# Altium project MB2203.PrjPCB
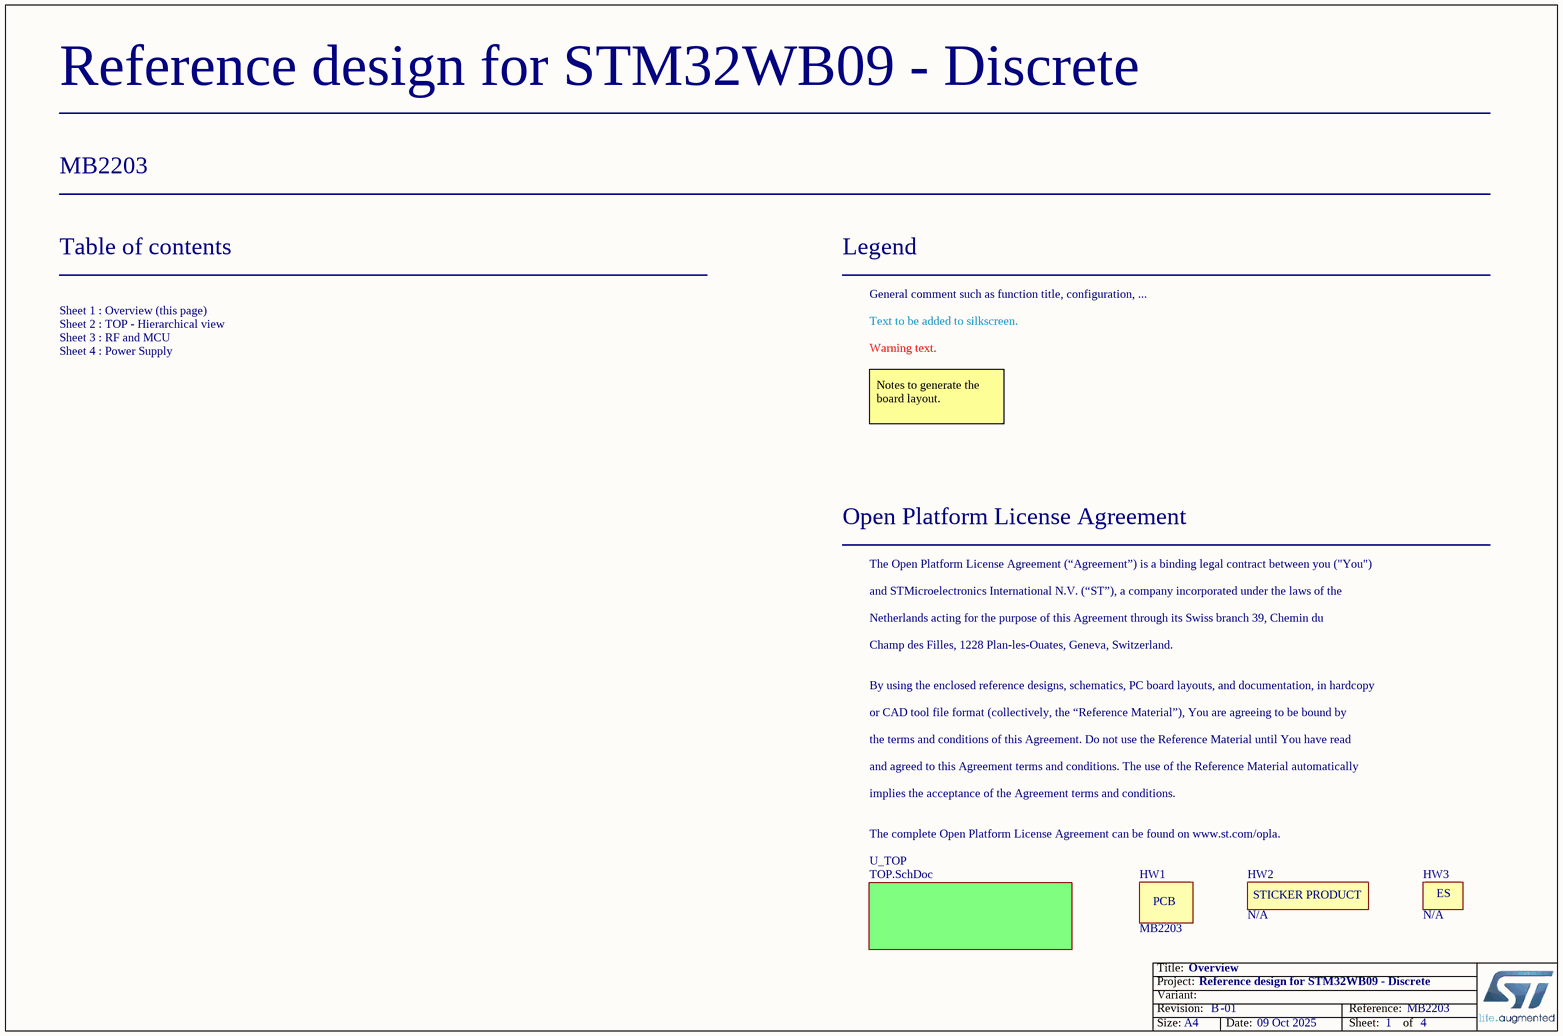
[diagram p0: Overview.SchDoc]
Board_Assembly_Revision: 01; Board_Document_Date: 09 Oct 2025; Board_Name: Reference design for STM32WB09 - Discrete; Board_PCB_Revision: B; Board_Reference: MB2203
4 sheets, 43 parts. Net scope: global (net labels, ports and power ports of the same name join across sheets).
Board file: MB2203.PcbDoc
Sheets:
  Overview.SchDoc
    U_TOP = TOP.SchDoc
      U_RF_MCU = RF_MCU.SchDoc
      U_Power_Supply = Power_Supply.SchDoc

## Sheet Overview.SchDoc: Overview
size A4; Date: Not used; ApprovedBy: Not used; CheckedBy: Not used; Author: Not used; CompanyName: STMicroelectronics; DrawnBy: Not used; Engineer: Not used; Organization: Not used; Address1: Not used; Address2: Not used; Address3: Not used; Address4: Not used; DocumentNumber: 1; Revision: Not used; SheetNumber: 1; SheetTotal: 4

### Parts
HW1  value MB2203  (hidden comment: PCB)
HW2  STICKER_PRODUCT  [STICKER_PRODUCT_25X9]  (value not drawn)  (no BOM)
HW3  STICKER_ES  [STICKER_ES_6X6]  (value not drawn)  (no BOM)

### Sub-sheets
U_TOP = TOP.SchDoc: no entries

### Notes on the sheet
- Table of contents
- Legend
- General comment such as function title, configuration, ...
- Text to be added to silkscreen.
- Warning text.
- Notes to generate the board layout.
- Open Platform License Agreement
- The Open Platform License Agreement (“Agreement”) is a binding legal contract between you ("You")
- and STMicroelectronics International N.V. (“ST”), a company incorporated under the laws of the
- Netherlands acting for the purpose of this Agreement through its Swiss branch 39, Chemin du
- Champ des Filles, 1228 Plan-les-Ouates, Geneva, Switzerland.
- Sheet 1 : Overview (this page)
  Sheet 2 : TOP - Hierarchical view
  Sheet 3 : RF and MCU
  Sheet 4 : Power Supply
- By using the enclosed reference designs, schematics, PC board layouts, and documentation, in hardcopy
- or CAD tool file format (collectively, the “Reference Material”), You are agreeing to be bound by
- the terms and conditions of this Agreement. Do not use the Reference Material until You have read
- and agreed to this Agreement terms and conditions. The use of the Reference Material automatically
- implies the acceptance of the Agreement terms and conditions.
- The complete Open Platform License Agreement can be found on www.st.com/opla.

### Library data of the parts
HW1 = MCD-04954: PCB, MB2203, 41x31mm, 4L1S, 0.638mm, TG150, VT-47; Part_Preference: Recommended; Manufacturer: SYNERGIE CAD; ShowFields: YES; ID: 7070
HW2 = MCD-00547: Sticker product, 25x9mm; Part_Type: Misc; Part_Preference: Recommended; Component_Country_Of_Origin: Unknown; ShowFields: YES; ID: 3197
HW3 = MCD-00234: Sticker ES, 6x6mm; Part_Type: Misc; Part_Preference: Recommended; Component_Country_Of_Origin: Unknown; ShowFields: YES; ID: 2634

## Sheet TOP.SchDoc: TOP - Hierarchical view
size A4; Date: Not used; ApprovedBy: Not used; CheckedBy: Not used; Author: Not used; CompanyName: STMicroelectronics; DrawnBy: Not used; Engineer: Not used; Organization: Not used; Address1: Not used; Address2: Not used; Address3: Not used; Address4: Not used; DocumentNumber: Not used; Revision: Not used; SheetNumber: 2; SheetTotal: 4
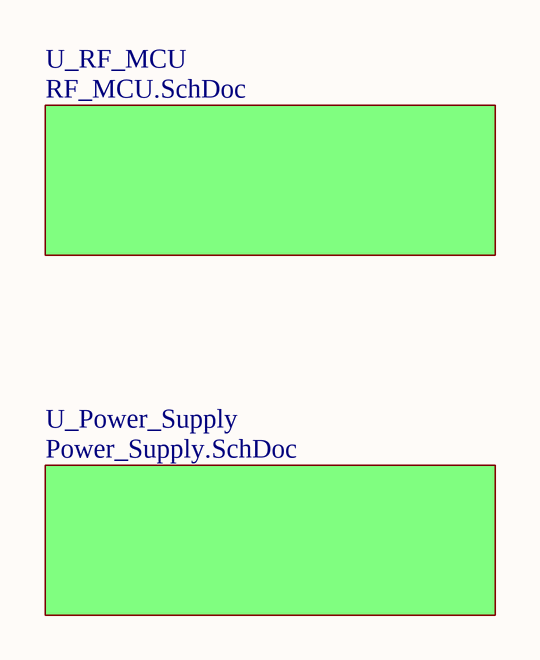
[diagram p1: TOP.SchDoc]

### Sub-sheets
U_Power_Supply = Power_Supply.SchDoc: no entries
U_RF_MCU = RF_MCU.SchDoc: no entries

## Sheet RF_MCU.SchDoc: RF and MCU
size A4; Date: Not used; ApprovedBy: Not used; CheckedBy: Not used; Author: Not used; CompanyName: STMicroelectronics; DrawnBy: Not used; Engineer: Not used; Organization: Not used; Address1: Not used; Address2: Not used; Address3: Not used; Address4: Not used; DocumentNumber: Not used; Revision: Not used; SheetNumber: 3; SheetTotal: 4
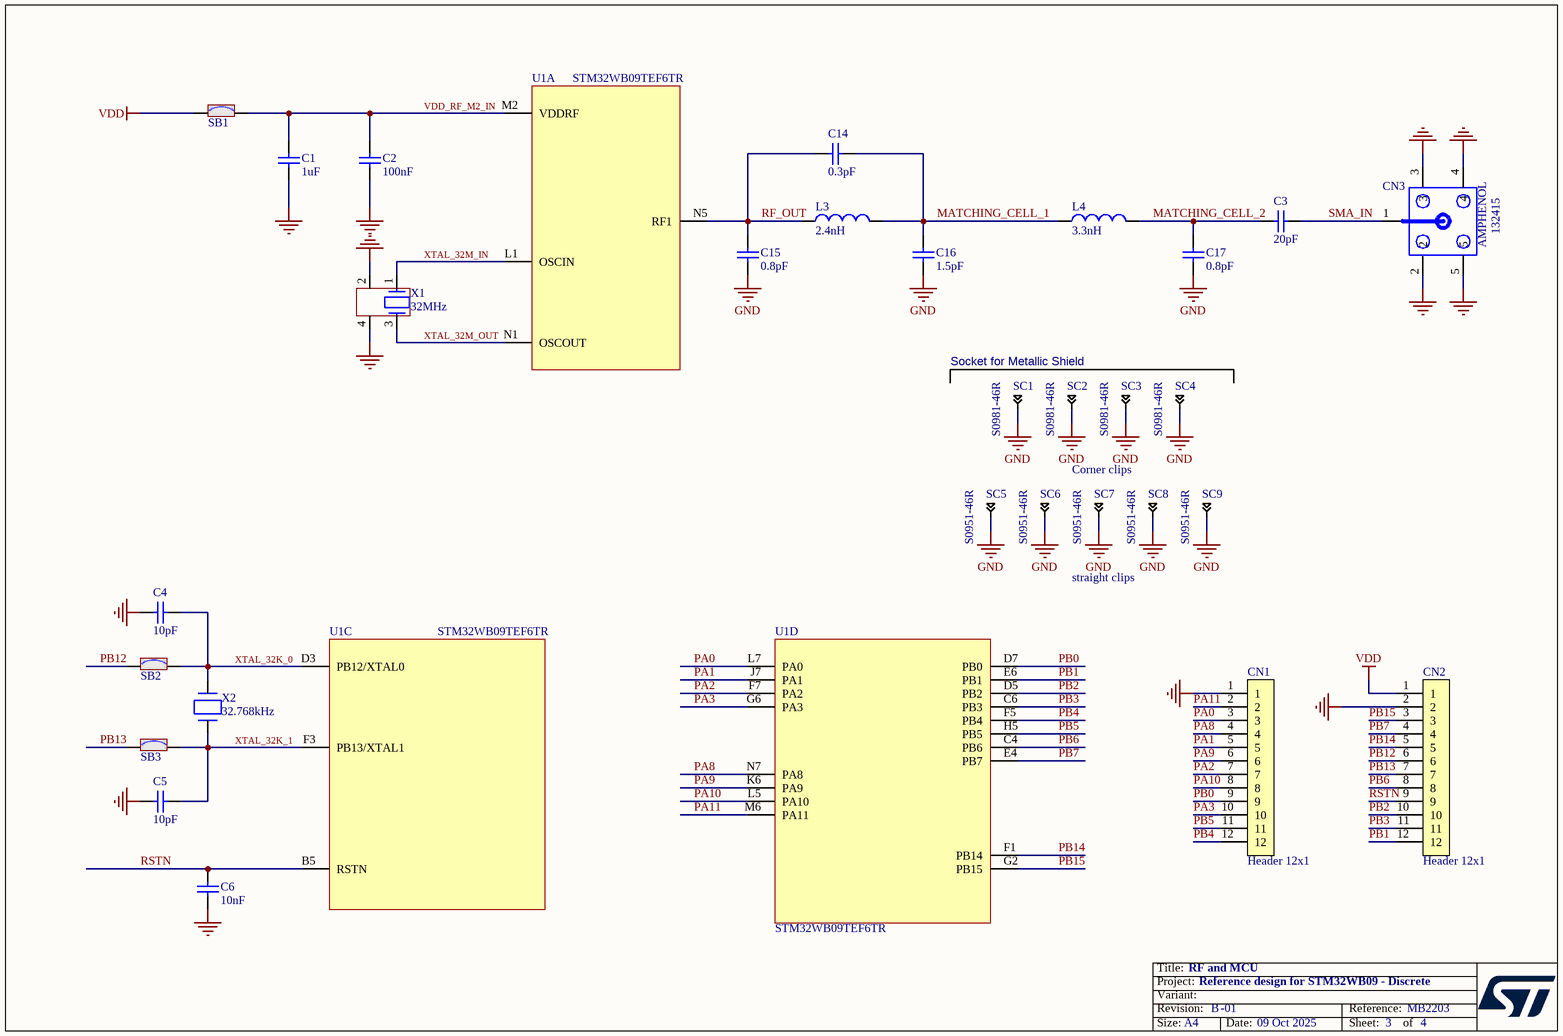
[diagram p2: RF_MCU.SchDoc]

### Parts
C1  value 1uF  [C0402]  (hidden comment: Capacitor)
C2  value 100nF  [C0201_H0P3]  (hidden comment: Capacitor)
C3  value 20pF  [C0201_H0P3]  (hidden comment: Capacitor)
C4  value 10pF  [C0402]  (hidden comment: Capacitor)
C5  value 10pF  [C0402]  (hidden comment: Capacitor)
C6  value 10nF  [C0402]  (hidden comment: Capacitor)
C14  value 0.3pF  [C0201_H0P3]  (hidden comment: Capacitor)
C15  value 0.8pF  [C0201_H0P3]  (hidden comment: Capacitor)
C16  value 1.5pF  [C0201_H0P3]  (hidden comment: Capacitor)
C17  value 0.8pF  [C0201_H0P3]  (hidden comment: Capacitor)
CN1  Header 12x1  [CON_SAMTEC_TSW-112-07-X-S]
CN2  Header 12x1  [CON_SAMTEC_TSW-112-07-X-S]
CN3  value 132415  Manufacturer: AMPHENOL  [CON_SMA_AMPHENOL_132415]  (hidden comment: SMA-J-P-H-ST-EM1)
L3  value 2.4nH  [IND_0201_MURATA_LQP03TN_H0P3]  (hidden comment: Inductor)
L4  value 3.3nH  [IND_0201_MURATA_LQP03TN_H0P3]  (hidden comment: Inductor)
SB1  SB_ON  [SOLDER-BRIDGE_R0402-0R]  (value not drawn)
SB2  SB_ON  [SOLDER-BRIDGE_R0402-0R]  (value not drawn)
SB3  SB_ON  [SOLDER-BRIDGE_R0402-0R]  (value not drawn)
SC1  value S0981-46R  [CLIP_HARWIN_S0981-46R]  (hidden comment: Shield-clip_S0951-46R)
SC2  value S0981-46R  [CLIP_HARWIN_S0981-46R]  (hidden comment: Shield-clip_S0951-46R)
SC3  value S0981-46R  [CLIP_HARWIN_S0981-46R]  (hidden comment: Shield-clip_S0951-46R)
SC4  value S0981-46R  [CLIP_HARWIN_S0981-46R]  (hidden comment: Shield-clip_S0951-46R)
SC5  value S0951-46R  [CLIP_HARWIN_S0951-46R]  (hidden comment: Shield-clip_S0951-46R)
SC6  value S0951-46R  [CLIP_HARWIN_S0951-46R]  (hidden comment: Shield-clip_S0951-46R)
SC7  value S0951-46R  [CLIP_HARWIN_S0951-46R]  (hidden comment: Shield-clip_S0951-46R)
SC8  value S0951-46R  [CLIP_HARWIN_S0951-46R]  (hidden comment: Shield-clip_S0951-46R)
SC9  value S0951-46R  [CLIP_HARWIN_S0951-46R]  (hidden comment: Shield-clip_S0951-46R)
U1  value STM32WB09TEF6TR  [ICC_WLCSP36_2P83X2P99_P040]  (hidden comment: IC_STM32WB09TEF6TR)  (parts A,C,D of 4)
X1  value 32MHz  [CRY_KYOCERA_CX2016DB_4P]  (hidden comment: XTAL_4_PINS)
X2  value 32.768kHz  [CRY_NX2012SA_2P]  (hidden comment: XTAL_2_PINS)

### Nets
GND: C1.1 C2.1 C4.2 C5.1 C6.2 C15.1 C16.1 C17.1 CN1.1 CN2.2 CN3.2 CN3.3 CN3.4 CN3.5 SC1.1 SC2.1 SC3.1 SC4.1 SC5.1 SC6.1 SC7.1 SC8.1 SC9.1 X1.2 X1.4
VDD: CN2.1 SB1.2
MATCHING_CELL_1: C14.2 C16.2 L3.2 L4.1
MATCHING_CELL_2: C3.1 C17.2 L4.2
PA0: CN1.3 U1.L7(PA0)
PA1: CN1.5 U1.J7(PA1)
PA2: CN1.7 U1.F7(PA2)
PA3: CN1.10 U1.G6(PA3)
PA8: CN1.4 U1.N7(PA8)
PA9: CN1.6 U1.K6(PA9)
PA10: CN1.8 U1.L5(PA10)
PA11: CN1.2 U1.M6(PA11)
PB0: CN1.9 U1.D7(PB0)
PB1: CN2.12 U1.E6(PB1)
PB2: CN2.10 U1.D5(PB2)
PB3: CN2.11 U1.C6(PB3)
PB4: CN1.12 U1.F5(PB4)
PB5: CN1.11 U1.H5(PB5)
PB6: CN2.8 U1.C4(PB6)
PB7: CN2.4 U1.E4(PB7)
PB12: CN2.6 SB2.2
PB13: CN2.7 SB3.2
PB14: CN2.5 U1.F1(PB14)
PB15: CN2.3 U1.G2(PB15)
RF_OUT: C14.1 C15.2 L3.1 U1.N5(RF1)
RSTN: C6.1 CN2.9 U1.B5(RSTN)
SMA_IN: C3.2 CN3.1
VDD_RF_M2_IN: C1.2 C2.2 SB1.1 U1.M2(VDDRF)
XTAL_32K_0: C4.1 SB2.1 U1.D3(PB12/XTAL0) X2.1(X1)
XTAL_32K_1: C5.2 SB3.1 U1.F3(PB13/XTAL1) X2.2(X2)
XTAL_32M_IN: U1.L1(OSCIN) X1.1
XTAL_32M_OUT: U1.N1(OSCOUT) X1.3

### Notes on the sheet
- Socket for Metallic Shield
- Corner clips
- straight clips

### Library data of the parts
C1 = MCD-03432: Capacitor, MLCC, 1uF, X7R, 6.3V,+/- 10%, 0402, T=0.5mm; Part_Preference: Recommended; Manufacturer: MURATA; Manufacturer_Part_Number: GRM155R70J105KA12; Order_Code_RS: 113-8711; ShowFields: YES; ID: 5548; Component_Country_Of_Origin: China, Japan, Philippines, Singapore
C2 = MCD-01535: Capacitor, MLCC,100nF, 10V, X5R, +/-10%, 0201, T=0.3mm; Part_Preference: Recommended; Manufacturer: MURATA; Manufacturer_Part_Number: GRM033R61A104KE15; Order_Code_RS: 790-2742; Component_Country_Of_Origin: Japan; ShowFields: YES; ID: 3635
C3 = MCD-03543: Capacitor, MLCC, 20pF, 25V, COG, +/-2%, 0201, T=0.3mm; Part_Preference: Recommended; Manufacturer: MURATA; Manufacturer_Part_Number: GJM0335C1E200GB01; ShowFields: YES; ID: 5659; Component_Country_Of_Origin: Japan, Singapore
C4 C5 = MCD-00015: Capacitor, MLCC, 10pF, 50V, NPO, +/-5%, 0402, T=0.5mm; Part_Preference: Recommended; Manufacturer: YAGEO; Manufacturer_Part_Number: CC0402JRNPO9BN100; Order_Code_RS: 3019160RL; Component_Country_Of_Origin: China; ShowFields: YES; ID: 2465
C6 = MCD-00011: Capacitor, MLCC, 10nF, 16V, X7R, +/-10%, 0402, T=0.5mm; Part_Preference: Recommended; Manufacturer: YAGEO; Manufacturer_Part_Number: CC0402KRX7R7BB103; Order_Code_RS: 3019275; Component_Country_Of_Origin: China; ShowFields: YES; ID: 2469
C14 = MCD-04945: Capacitor, MLCC, 0.3pF, 25V, COG, +/-0.05pF, 0201, T=0.3mm; Part_Preference: Recommended; Manufacturer: MURATA; Manufacturer_Part_Number: GJM0335C1ER30WB01D; Order_Code_RS: NA; ShowFields: YES; ID: 7061
C15 C17 = MCD-04946: Capacitor, MLCC, 0.8pF, 25V, +/- 0.05pF, C0G (NP0), 0201; Part_Preference: Recommended; Manufacturer: MURATA; Manufacturer_Part_Number: GJM0335C1ER80WB01D; Order_Code_RS: NA; ShowFields: YES; ID: 7062
C16 = MCD-04947: Capacitor, MLCC, 1.5pF, 25V, COG, +/-0.1pF, 0201; Part_Preference: Recommended; Manufacturer: MURATA; Manufacturer_Part_Number: GJM0335C1E1R5BB01D; Order_Code_RS: NA; ShowFields: YES; ID: 7063
CN1 CN2 = MCD-01795: Header, 12x1, 2.54mm, VR, TH, T=5.84mm/2.54mm; Part_Type: Connector; Part_Preference: Recommended; Manufacturer: SAMTEC; Manufacturer_Part_Number: TSW-112-07-T-S; Order_Code_RS: 180-2023; Component_Country_Of_Origin: China, Costa Rica, Malaysia, United States, Vietnam; ShowFields: YES; ID: 3895
CN3 = MCD-04961: Jack_SMA, VR, PCB edge, 50R, T=7.92mm; Part_Type: Connector; Part_Preference: Recommended; Order_Code_RS: NA; ShowFields: YES; ID: 7077
L3 = MCD-04955: Inductor, 2.4nH, +/-0.1nH, 500mA, 200mR, 0201, T=0.33mm; Part_Preference: Recommended; Manufacturer: MURATA; Manufacturer_Part_Number: LQP03TN2N4B02D; Order_Code_RS: NA; ShowFields: YES; ID: 7071
L4 = MCD-02439: Inductor, 3.3nH, +/-0.1nH, 450mA, 250mR, 0201, T=0.33mm; Part_Preference: Recommended; Manufacturer: MURATA; Manufacturer_Part_Number: LQP03TN3N3B02D; Order_Code_RS: 166-9756; Component_Country_Of_Origin: Japan°; ShowFields: YES; ID: 4545
SB1-SB3 = MCD-01618: Resistor, 0R, SB0402, 5%, 0.063W; Part_Preference: Recommended; Manufacturer: YAGEO; Manufacturer_Part_Number: RC0402JR-070RL; Order_Code_RS: 618-5804; Component_Country_Of_Origin: China; ShowFields: YES; ID: 3718
SC1-SC4 = MCD-02164: Shield clip Harwin S0981-46R to fix RF shielded cavity; Part_Type: Mechanical; Part_Preference: Recommended; Order_Code_RS: 161-3702; Component_Country_Of_Origin: South Korea; ShowFields: YES; ID: 4264
SC5-SC9 = MCD-01587: RFI shield clip mini TIN SMD; Part_Type: Mechanical; Part_Preference: Recommended; Manufacturer: HARWIN; Component_Country_Of_Origin: South Korea; ShowFields: YES; ID: 3687
U1 = MCD-04889: MCU, ARM Cortex-M0+ 32-bit, 512KB Flash, 64KB RAM, With Crypto; Part_Type: IC; Part_Preference: Recommended; Manufacturer: STMICROELECTRONICS; Order_Code_RS: 215-118; ShowFields: YES; ID: 7005
X1 = MCD-05065: Crystal, 32MHz, 8pF, +/-40ppm, 60R, 2x1.6mm; Part_Type: Crystal_Osc; Part_Preference: Recommended; Manufacturer: KYOCERA; Manufacturer_Part_Number: CX2016DB32000D0WZRC1; ShowFields: YES; ID: 7181
X2 = MCD-01445: Crystal, 32.768kHz, 7pF, +/-20ppm, 80K, 2.05x1.2mm; BMS_Part_Number: 9157043; Part_Type: Crystal_Osc; Part_Preference: Recommended; Manufacturer: NDK; Manufacturer_Part_Number: NX2012SA-32.768KHZ-EXS00A-MU00389; Component_Country_Of_Origin: Unknown; ShowFields: YES; ID: 3545

## Sheet Power_Supply.SchDoc: Power Supply
size A4; Date: Not used; ApprovedBy: Not used; CheckedBy: Not used; Author: Not used; CompanyName: STMicroelectronics; DrawnBy: Not used; Engineer: Not used; Organization: Not used; Address1: Not used; Address2: Not used; Address3: Not used; Address4: Not used; DocumentNumber: Not used; Revision: Not used; SheetNumber: 4; SheetTotal: 4
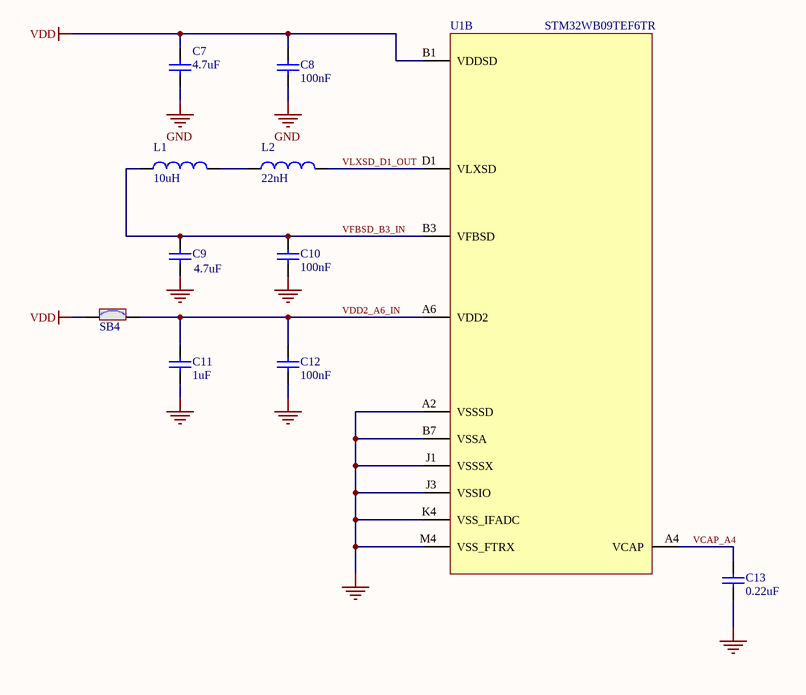
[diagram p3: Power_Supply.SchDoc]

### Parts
C7  value 4.7uF  [C0402]  (hidden comment: Capacitor)
C8  value 100nF  [C0201_H0P3]  (hidden comment: Capacitor)
C9  value 4.7uF  [C0402]  (hidden comment: Capacitor)
C10  value 100nF  [C0201_H0P3]  (hidden comment: Capacitor)
C11  value 1uF  [C0402]  (hidden comment: Capacitor)
C12  value 100nF  [C0201_H0P3]  (hidden comment: Capacitor)
C13  value 0.22uF  [C0402]  (hidden comment: Capacitor)
L1  value 10uH  [IND_0805_MURATA_LQM21]  (hidden comment: Inductor)
L2  value 22nH  [IND_0402_H0P5]  (hidden comment: Inductor)
SB4  SB_ON  [SOLDER-BRIDGE_R0402-0R]  (value not drawn)
U1  value STM32WB09TEF6TR  [ICC_WLCSP36_2P83X2P99_P040]  (hidden comment: IC_STM32WB09TEF6TR)  (part B of 4)

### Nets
GND: C7.1 C8.1 C9.1 C10.1 C11.1 C12.1 C13.1 U1.A2(VSSSD) U1.B7(VSSA) U1.J1(VSSSX) U1.J3(VSSIO) U1.K4(VSS_IFADC) U1.M4(VSS_FTRX)
VDD: C7.2 C8.2 SB4.2 U1.B1(VDDSD)
VCAP_A4: C13.2 U1.A4(VCAP)
VDD2_A6_IN: C11.2 C12.2 SB4.1 U1.A6(VDD2)
VFBSD_B3_IN: C9.2 C10.2 L1.1 U1.B3(VFBSD)
VLXSD_D1_OUT: L2.2 U1.D1(VLXSD)
NetL1_2: L1.2 L2.1

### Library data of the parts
C7 C9 = MCD-03431: Capacitor, MLCC, 4.7uF, X5R, 10V, +/-20%, 0402, T=0.5mm; Part_Preference: Recommended; Manufacturer: MURATA; Manufacturer_Part_Number: GRM155R61A475MEAAD; Order_Code_RS: 172-6870; ShowFields: YES; ID: 5547; Component_Country_Of_Origin: China, Japan, Philippines, Singapore
C8 C10 C12 = MCD-01535: as C2 on sheet RF_MCU
C11 = MCD-03432: as C1 on sheet RF_MCU
C13 = MCD-03483: Capacitor, MLCC, 0.22uF, X5R, 6.3V, +/-10%, 0402, T=0.5mm; Part_Preference: Recommended; Manufacturer: YAGEO; Manufacturer_Part_Number: CC0402KRX5R5BB224; Order_Code_RS: 3369131; ShowFields: YES; ID: 5599; Component_Country_Of_Origin: China
L1 = MCD-03438: Inductor, MLCC, 10uH, +/-20%, 300mA, 845mR, 0805, T=1.45mm; Part_Preference: Recommended; Manufacturer: MURATA; Manufacturer_Part_Number: LQM21DN100M70L; Order_Code_RS: NA; ShowFields: YES; ID: 5554; Component_Country_Of_Origin: Japan
L2 = MCD-03439: Inductor, MLCC, 22nH, +/-2%, 350mA, 0.58R, 0402, T=1.45mm; Part_Preference: Recommended; Manufacturer: MURATA; Manufacturer_Part_Number: LQW15AN22NG00; Order_Code_RS: 3354168; ShowFields: YES; ID: 5555; Component_Country_Of_Origin: Japan
SB4 = MCD-01618: as SB1 on sheet RF_MCU
U1 = MCD-04889: as U1 on sheet RF_MCU

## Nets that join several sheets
GND: RF_MCU (25 pins), Power_Supply (13 pins)
VDD: RF_MCU (CN2.1 SB1.2), Power_Supply (C7.2 C8.2 SB4.2 U1.B1)

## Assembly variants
WB09TF4LD: not fitted C2 C16 CN1 CN2 SB2 SB3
